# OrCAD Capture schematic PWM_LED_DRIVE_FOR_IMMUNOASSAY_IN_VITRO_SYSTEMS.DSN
size A; title: PWM LED driver for Immunoassay In Vitro Diagnostic System; rev: 1.0; note: N/A
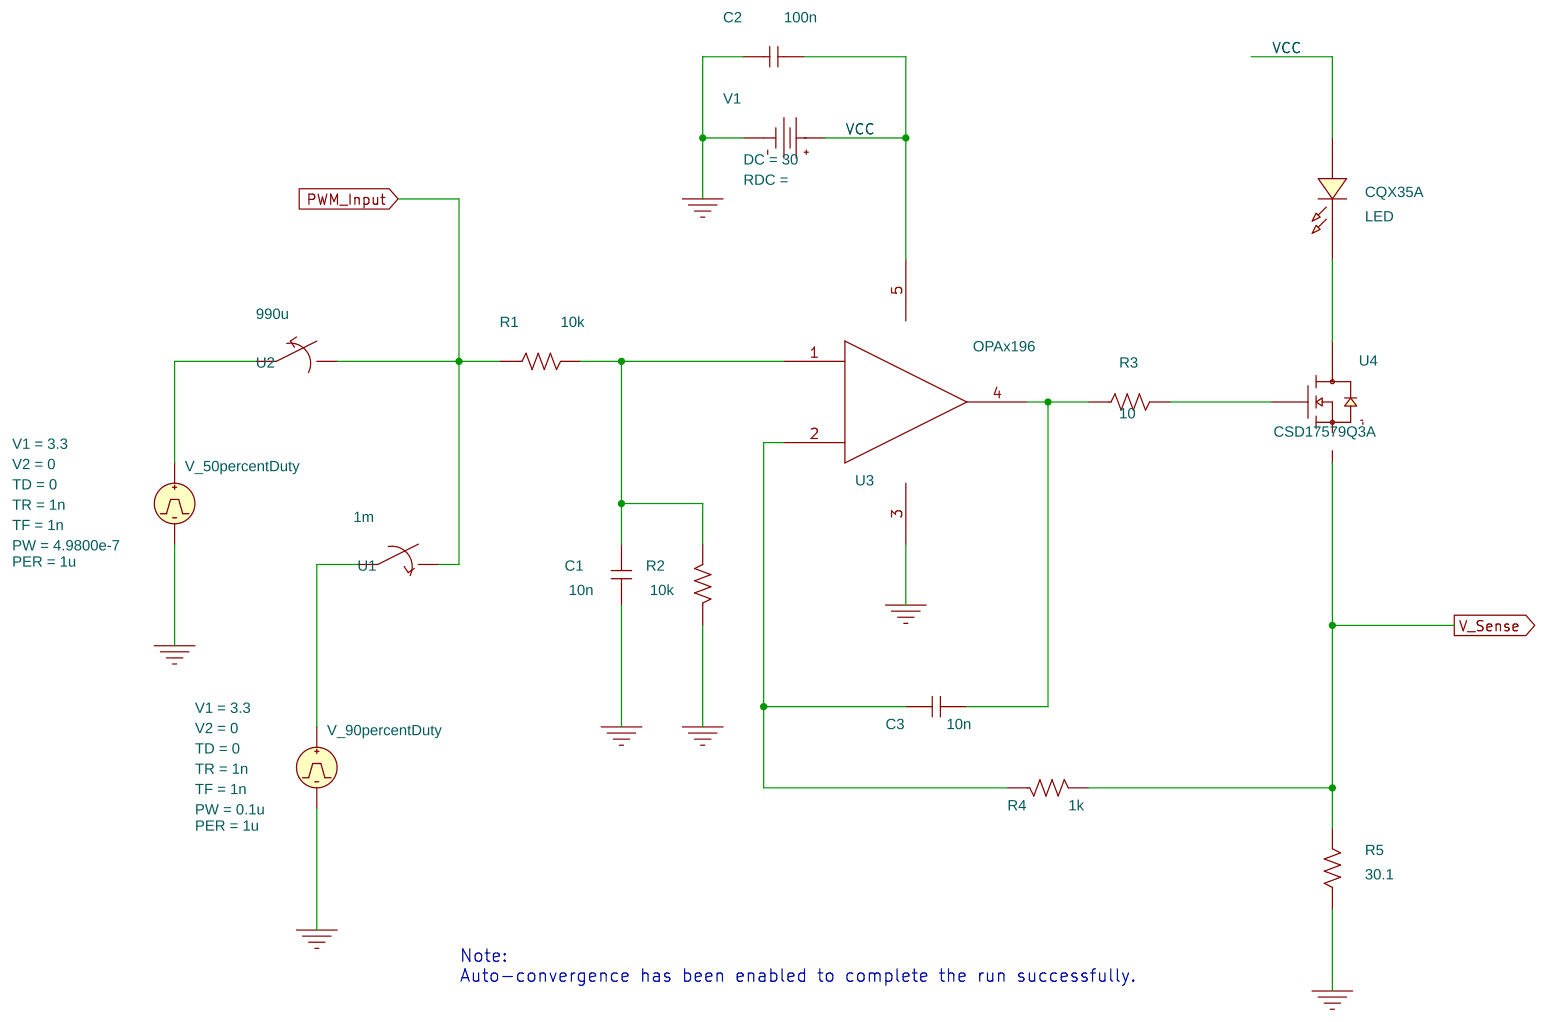
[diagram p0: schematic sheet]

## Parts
C1  10n  [cap196]
C2  100n  [cap196]
C3  10n  [cap196]
LED  CQX35A  [DO41]
R1  10k  [AXRC05]
R2  10k  [AXRC05]
R3  10  [AXRC05]
R4  1k  [AXRC05]
R5  30.1  [AXRC05]
U1  Sw_tClose
U2  Switch Opens at T
U3  OPAx196
U4  CSD17579Q3A
V1  VDC
V_50percentDuty  VPULSE
V_90percentDuty  VPULSE

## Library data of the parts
C1-C3 = C
LED = CQX35A
R1-R5 = R
U1 = Sw_tClose: RCLOSED: 1; ROPEN: 1G; TCLOSE: 1m
U2 = Sw_tOpen: ROPEN: 1G; TOPEN: 990u
U3 = OPAx196
U4 = CSD17579Q3A
V1 = VDCR: AppProp: DC$Voltage$1$-1; DC: 30
V_50percentDuty = VPULSE: AC: 0; AppProp: Pulse$Voltage$2$-1; DC: 0; PER: 1u; PW: 4.9800e-7; TD: 0; TF: 1n; TR: 1n; V1: 3.3; V2: 0
V_90percentDuty = VPULSE: AC: 0; AppProp: Pulse$Voltage$1$-1; DC: 0; PER: 1u; PW: 0.1u; TD: 0; TF: 1n; TR: 1n; V1: 3.3; V2: 0

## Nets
VCC: C2.2 LED.1 U3.5(VCC) V1.0(+)
0: C1.1 C2.1 R2.1 R5.1 U3.3(VEE) V1.1(-) V_50percentDuty.2(-) V_90percentDuty.2(-)
PWM_Input: R1.1 U1.2 U2.2
V_Sense: R4.2 R5.2 U4.1(source)
N00589: C1.2 R1.2 R2.2 U3.1(IN+)
N00870: U2.1 V_50percentDuty.1(+)
N00986: U1.1 V_90percentDuty.1(+)
N01335: C3.1 R4.1 U3.2(IN-)
N01347: C3.2 R3.1 U3.4(OUT)
N01593: R3.2 U4.2(gate)
N01597: LED.2 U4.3(drain)

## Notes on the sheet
- Note:
  Auto-convergence has been enabled to complete the run successfully.
